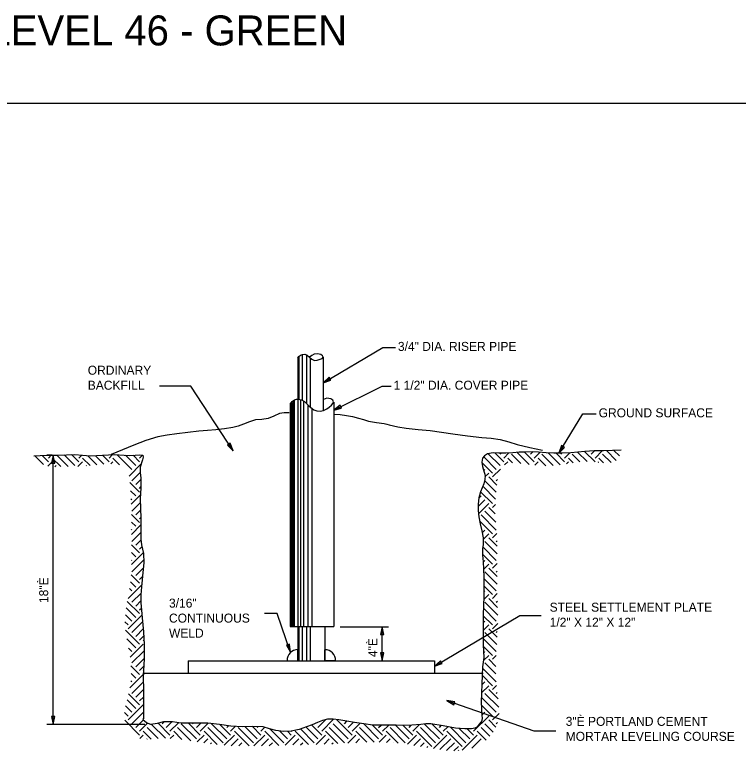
# Model space of a CAD drawing. Extents: x -439.1 to -407.9, y -458.1 to -436.2.
# Drawn here: x -426.04 to -413.98, y -448.69 to -436.2 of the extents above; entities that cross this region are included whole.
import ezdxf

# ---------------------------------------------------------------- set-up
doc = ezdxf.new("R2010")
doc.units = 0
for name, color, linetype in [('Bridge-Named Boundary', 7, 'Continuous'), ('Default', 7, 'Continuous'), ('Level 4', 7, 'Continuous'), ('Level 46', 7, 'Continuous')]:
    doc.layers.add(name, color=color, linetype=linetype)

msp = doc.modelspace()

# ---------------------------------------------------------------- linework, layer by layer
at = {"layer": 'Bridge-Named Boundary'}
msp.add_lwpolyline([(-439.109, -458.051), (-407.859, -458.051), (-407.859, -437.676), (-439.109, -437.676)], close=True, dxfattribs=at)
at = {"layer": 'Default'}
for p, q in [((-420.903, -442.33), (-419.904, -441.741)), ((-419.904, -441.741), (-419.695, -441.741)), ((-421.306, -441.894), (-421.306, -442.605)), ((-421.254, -441.859), (-421.254, -442.619)), ((-421.18, -441.866), (-421.18, -442.673)), ((-421.116, -441.915), (-421.116, -442.739)), ((-420.903, -442.33), (-420.79, -442.263)), ((-420.79, -442.263), (-420.903, -442.33)), ((-423.108, -442.387), (-423.634, -442.387)), ((-422.404, -443.465), (-423.108, -442.387)), ((-420.725, -442.79), (-419.918, -442.387)), ((-419.918, -442.387), (-419.767, -442.387)), ((-421.324, -442.604), (-421.324, -446.398)), ((-421.429, -442.664), (-421.429, -446.398)), ((-421.408, -442.642), (-421.408, -446.398)), ((-421.387, -442.623), (-421.387, -446.398)), ((-421.282, -442.61), (-421.282, -446.398)), ((-421.23, -442.632), (-421.23, -446.398)), ((-421.156, -442.698), (-421.156, -446.398)), ((-421.092, -442.76), (-421.092, -446.398)), ((-420.725, -442.79), (-420.607, -442.731)), ((-420.607, -442.731), (-420.725, -442.79)), ((-416.971, -443.507), (-416.57, -442.847)), ((-416.57, -442.847), (-416.347, -442.847)), ((-422.404, -443.465), (-422.476, -443.355)), ((-422.476, -443.355), (-422.404, -443.465)), ((-416.902, -443.394), (-416.971, -443.507)), ((-416.971, -443.507), (-416.902, -443.394)), ((-416.368, -443.649), (-416.542, -443.476)), ((-416.432, -443.523), (-416.38, -443.47)), ((-416.368, -443.586), (-416.249, -443.466)), ((-416.013, -443.625), (-416.174, -443.463)), ((-415.959, -443.552), (-416.052, -443.459)), ((-415.989, -443.459), (-415.986, -443.457)), ((-425.565, -443.695), (-425.711, -443.549)), ((-425.484, -443.649), (-425.59, -443.543)), ((-425.424, -443.539), (-425.511, -443.539)), ((-425.484, -443.586), (-425.437, -443.539)), ((-425.277, -443.729), (-425.421, -443.586)), ((-425.403, -448.028), (-425.403, -443.539)), ((-425.153, -443.727), (-425.341, -443.539)), ((-425.041, -443.712), (-425.22, -443.534)), ((-424.978, -443.649), (-425.099, -443.528)), ((-424.978, -443.586), (-424.929, -443.538)), ((-424.788, -443.712), (-424.914, -443.586)), ((-424.674, -443.7), (-424.826, -443.547)), ((-424.559, -443.688), (-424.699, -443.548)), ((-424.471, -443.649), (-424.581, -443.54)), ((-424.471, -443.586), (-424.414, -443.528)), ((-424.296, -443.698), (-424.408, -443.586)), ((-424.091, -443.776), (-424.337, -443.531)), ((-424.028, -443.712), (-424.199, -443.541)), ((-423.965, -443.649), (-424.073, -443.541)), ((-423.965, -443.586), (-423.917, -443.538)), ((-418.014, -443.776), (-418.223, -443.567)), ((-417.951, -443.712), (-418.148, -443.515)), ((-417.888, -443.649), (-418.034, -443.503)), ((-417.951, -443.523), (-417.935, -443.507)), ((-417.888, -443.586), (-417.804, -443.502)), ((-417.742, -443.668), (-417.824, -443.586)), ((-417.607, -443.677), (-417.761, -443.523)), ((-417.464, -443.693), (-417.664, -443.493)), ((-417.381, -443.649), (-417.543, -443.487)), ((-417.445, -443.523), (-417.408, -443.486)), ((-417.381, -443.586), (-417.284, -443.488)), ((-417.189, -443.714), (-417.318, -443.586)), ((-417.066, -443.711), (-417.255, -443.523)), ((-416.95, -443.7), (-417.15, -443.5)), ((-416.875, -443.649), (-417.017, -443.507)), ((-416.938, -443.523), (-416.923, -443.507)), ((-416.875, -443.586), (-416.787, -443.498)), ((-416.732, -443.665), (-416.812, -443.586)), ((-416.622, -443.649), (-416.748, -443.523)), ((-416.499, -443.646), (-416.658, -443.486)), ((-416.224, -443.667), (-416.305, -443.586)), ((-416.101, -443.663), (-416.242, -443.523)), ((-425.494, -443.722), (-425.421, -443.649)), ((-425.378, -443.733), (-425.357, -443.712)), ((-424.991, -443.726), (-424.914, -443.649)), ((-424.857, -443.718), (-424.851, -443.712)), ((-424.443, -443.684), (-424.408, -443.649)), ((-424.139, -443.887), (-423.936, -443.683)), ((-418.078, -443.839), (-418.254, -443.663)), ((-417.878, -443.702), (-417.824, -443.649)), ((-417.372, -443.703), (-417.318, -443.649)), ((-416.846, -443.683), (-416.812, -443.649)), ((-416.313, -443.657), (-416.305, -443.649)), ((-424.091, -443.966), (-423.955, -443.83)), ((-418.221, -443.793), (-418.204, -443.776)), ((-418.204, -443.902), (-418.141, -443.839)), ((-418.078, -443.902), (-417.945, -443.77)), ((-424.028, -444.029), (-423.942, -443.942)), ((-418.015, -444.154), (-418.204, -443.966)), ((-418.003, -444.04), (-418.141, -443.902)), ((-418.014, -443.966), (-417.992, -443.943)), ((-423.965, -444.156), (-424.127, -443.993)), ((-423.965, -444.092), (-423.94, -444.068)), ((-418.026, -444.271), (-418.239, -444.057)), ((-424.028, -444.219), (-424.116, -444.131)), ((-424.103, -444.357), (-423.948, -444.202)), ((-418.301, -444.252), (-418.268, -444.219)), ((-418.078, -444.345), (-418.275, -444.148)), ((-424.091, -444.282), (-424.107, -444.267)), ((-424.091, -444.472), (-423.953, -444.334)), ((-418.317, -444.395), (-418.204, -444.282)), ((-418.311, -444.516), (-418.141, -444.345)), ((-424.028, -444.535), (-423.948, -444.456)), ((-418.022, -444.654), (-418.204, -444.472)), ((-418.031, -444.519), (-418.141, -444.409)), ((-418.078, -444.409), (-418.03, -444.361)), ((-423.965, -444.662), (-424.099, -444.528)), ((-423.965, -444.599), (-423.942, -444.576)), ((-418.014, -444.789), (-418.268, -444.535)), ((-424.1, -444.86), (-423.942, -444.702)), ((-424.028, -444.725), (-424.098, -444.655)), ((-418.078, -444.852), (-418.291, -444.639)), ((-418.27, -444.728), (-418.268, -444.725)), ((-424.091, -444.789), (-424.099, -444.781)), ((-424.091, -444.978), (-423.942, -444.829)), ((-418.248, -444.833), (-418.204, -444.789)), ((-418.233, -444.944), (-418.141, -444.852)), ((-418.078, -444.915), (-418.006, -444.844)), ((-424.028, -445.042), (-423.939, -444.953)), ((-417.998, -445.185), (-418.204, -444.978)), ((-418, -445.057), (-418.141, -444.915)), ((-418.014, -444.978), (-418.001, -444.965)), ((-423.965, -445.168), (-424.099, -445.034)), ((-423.965, -445.105), (-423.925, -445.065)), ((-418.014, -445.295), (-418.239, -445.07)), ((-424.028, -445.232), (-424.098, -445.162)), ((-424.097, -445.364), (-423.902, -445.169)), ((-418.078, -445.358), (-418.245, -445.191)), ((-424.091, -445.295), (-424.096, -445.29)), ((-424.091, -445.485), (-423.896, -445.29)), ((-418.233, -445.323), (-418.204, -445.295)), ((-418.078, -445.422), (-417.999, -445.343)), ((-424.028, -445.548), (-423.903, -445.423)), ((-418.228, -445.445), (-418.141, -445.358)), ((-418.002, -445.561), (-418.141, -445.422)), ((-418.014, -445.485), (-418.001, -445.471)), ((-423.965, -445.675), (-424.105, -445.534)), ((-423.965, -445.612), (-423.916, -445.563)), ((-418.014, -445.801), (-418.222, -445.593)), ((-418.001, -445.688), (-418.204, -445.485)), ((-424.155, -445.928), (-423.928, -445.702)), ((-424.028, -445.738), (-424.113, -445.653)), ((-418.078, -445.865), (-418.222, -445.72)), ((-424.091, -445.801), (-424.129, -445.764)), ((-424.091, -445.991), (-423.938, -445.838)), ((-418.222, -445.82), (-418.204, -445.801)), ((-418.078, -445.928), (-417.998, -445.848)), ((-424.028, -446.055), (-423.941, -445.968)), ((-418.224, -445.948), (-418.141, -445.865)), ((-417.992, -446.077), (-418.141, -445.928)), ((-418.014, -445.991), (-417.995, -445.972)), ((-424.028, -446.245), (-424.186, -446.087)), ((-423.965, -446.181), (-424.168, -445.978)), ((-423.965, -446.118), (-423.934, -446.088)), ((-418.014, -446.308), (-418.23, -446.092)), ((-417.991, -446.205), (-418.204, -445.991)), ((-424.091, -446.308), (-424.2, -446.2)), ((-424.155, -446.434), (-423.925, -446.205)), ((-421.671, -446.181), (-421.88, -446.181)), ((-421.446, -446.827), (-421.671, -446.181)), ((-419.043, -447.058), (-417.619, -446.21)), ((-418.078, -446.371), (-418.233, -446.216)), ((-417.619, -446.21), (-417.267, -446.21)), ((-424.155, -446.371), (-424.207, -446.319)), ((-424.091, -446.498), (-423.915, -446.321)), ((-418.233, -446.337), (-418.204, -446.308)), ((-418.078, -446.434), (-417.991, -446.348)), ((-423.965, -446.688), (-424.197, -446.455)), ((-424.028, -446.561), (-423.904, -446.437)), ((-421.306, -446.398), (-421.306, -446.967)), ((-421.254, -446.398), (-421.254, -446.967)), ((-421.18, -446.398), (-421.18, -446.967)), ((-421.116, -446.398), (-421.116, -446.967)), ((-420.62, -446.399), (-419.811, -446.399)), ((-419.915, -446.966), (-419.915, -446.399)), ((-418.234, -446.464), (-418.141, -446.371)), ((-418.001, -446.574), (-418.141, -446.434)), ((-423.965, -446.624), (-423.896, -446.556)), ((-418.014, -446.814), (-418.235, -446.594)), ((-418.006, -446.696), (-418.204, -446.498)), ((-418.014, -446.498), (-417.997, -446.48)), ((-424.028, -446.751), (-424.175, -446.604)), ((-424.122, -446.908), (-423.901, -446.688)), ((-423.892, -446.634), (-423.901, -446.624)), ((-421.49, -446.7), (-421.447, -446.825)), ((-421.447, -446.825), (-421.49, -446.7)), ((-418.078, -446.878), (-418.231, -446.724)), ((-424.091, -446.814), (-424.146, -446.759)), ((-424.091, -447.004), (-423.889, -446.802)), ((-421.324, -446.967), (-421.324, -446.781)), ((-420.873, -446.967), (-420.873, -446.784)), ((-418.224, -446.834), (-418.204, -446.814)), ((-424.028, -447.067), (-423.889, -446.929)), ((-421.505, -446.967), (-421.324, -446.967)), ((-420.694, -446.967), (-420.873, -446.967)), ((-418.228, -446.964), (-418.141, -446.878)), ((-418.021, -447.061), (-418.141, -446.941)), ((-418.078, -446.941), (-418.014, -446.877)), ((-423.965, -447.194), (-424.109, -447.05)), ((-423.965, -447.131), (-423.896, -447.062)), ((-418.015, -447.32), (-418.245, -447.09)), ((-418.02, -447.188), (-418.204, -447.004)), ((-424.125, -447.418), (-423.901, -447.194)), ((-424.028, -447.257), (-424.105, -447.18)), ((-423.9, -447.133), (-423.901, -447.131)), ((-418.078, -447.384), (-418.252, -447.209)), ((-424.091, -447.321), (-424.109, -447.303)), ((-424.091, -447.511), (-423.9, -447.319)), ((-418.254, -447.371), (-418.204, -447.321)), ((-424.028, -447.574), (-423.9, -447.446)), ((-418.26, -447.503), (-418.141, -447.384)), ((-417.985, -447.603), (-418.141, -447.447)), ((-418.078, -447.447), (-418.012, -447.382)), ((-423.965, -447.701), (-424.146, -447.519)), ((-423.965, -447.637), (-423.9, -447.572)), ((-418.014, -447.827), (-418.263, -447.579)), ((-417.971, -447.744), (-418.204, -447.511)), ((-418.014, -447.511), (-417.998, -447.495)), ((-424.091, -447.827), (-424.198, -447.721)), ((-424.028, -447.764), (-424.172, -447.619)), ((-424.155, -447.954), (-423.901, -447.701)), ((-423.9, -447.639), (-423.901, -447.637)), ((-418.84, -447.632), (-417.389, -448.135)), ((-418.84, -447.632), (-418.716, -447.676)), ((-418.716, -447.676), (-418.84, -447.632)), ((-418.078, -447.89), (-418.262, -447.706)), ((-424.155, -447.89), (-424.216, -447.829)), ((-424.091, -448.017), (-423.9, -447.826)), ((-418.254, -447.877), (-418.204, -447.827)), ((-418.078, -447.954), (-417.969, -447.846)), ((-423.965, -448.207), (-424.212, -447.96)), ((-424.028, -448.08), (-423.906, -447.958)), ((-420.99, -448.08), (-420.861, -447.952)), ((-420.926, -448.144), (-420.727, -447.944)), ((-420.42, -448.207), (-420.673, -447.954)), ((-420.546, -448.017), (-420.506, -447.976)), ((-418.394, -448.144), (-418.141, -447.89)), ((-418.02, -448.075), (-418.141, -447.954)), ((-423.878, -448.028), (-425.511, -448.028)), ((-423.965, -448.144), (-423.829, -448.008)), ((-423.653, -448.266), (-423.838, -448.08)), ((-423.532, -448.26), (-423.764, -448.028)), ((-423.458, -448.207), (-423.655, -448.011)), ((-423.585, -448.017), (-423.554, -447.986)), ((-423.522, -448.08), (-423.427, -447.986)), ((-423.458, -448.144), (-423.315, -448.001)), ((-423.111, -448.301), (-423.332, -448.08)), ((-423.015, -448.27), (-423.268, -448.017)), ((-422.952, -448.207), (-423.148, -448.011)), ((-423.079, -448.017), (-423.07, -448.008)), ((-423.015, -448.08), (-422.943, -448.008)), ((-422.952, -448.144), (-422.819, -448.011)), ((-422.572, -448.334), (-422.825, -448.08)), ((-422.509, -448.27), (-422.762, -448.017)), ((-422.446, -448.207), (-422.624, -448.029)), ((-422.509, -448.08), (-422.478, -448.05)), ((-422.446, -448.144), (-422.363, -448.061)), ((-422.066, -448.334), (-422.319, -448.08)), ((-422.002, -448.27), (-422.204, -448.068)), ((-421.939, -448.207), (-422.083, -448.063)), ((-422.002, -448.08), (-421.985, -448.063)), ((-421.939, -448.144), (-421.873, -448.077)), ((-420.99, -448.27), (-421.186, -448.073)), ((-420.926, -448.207), (-421.096, -448.037)), ((-420.546, -448.334), (-420.8, -448.08)), ((-420.483, -448.27), (-420.736, -448.017)), ((-420.483, -448.08), (-420.396, -447.994)), ((-420.42, -448.144), (-420.288, -448.012)), ((-420.049, -448.324), (-420.293, -448.08)), ((-419.977, -448.27), (-420.224, -448.022)), ((-419.913, -448.207), (-420.083, -448.038)), ((-419.977, -448.08), (-419.936, -448.04)), ((-419.913, -448.144), (-419.808, -448.039)), ((-419.534, -448.334), (-419.787, -448.08)), ((-419.47, -448.27), (-419.697, -448.044)), ((-419.407, -448.207), (-419.565, -448.049)), ((-419.47, -448.08), (-419.434, -448.044)), ((-419.407, -448.144), (-419.294, -448.03)), ((-419.027, -448.334), (-419.28, -448.08)), ((-418.964, -448.27), (-419.21, -448.024)), ((-418.901, -448.207), (-419.088, -448.019)), ((-418.964, -448.08), (-418.927, -448.044)), ((-418.901, -448.144), (-418.824, -448.067)), ((-418.521, -448.334), (-418.774, -448.08)), ((-418.457, -448.27), (-418.632, -448.095)), ((-418.121, -448.227), (-418.268, -448.08)), ((-418.064, -448.157), (-418.204, -448.017)), ((-418.014, -448.017), (-417.993, -447.995)), ((-423.958, -448.263), (-423.901, -448.207)), ((-423.771, -448.274), (-423.901, -448.144)), ((-423.451, -448.263), (-423.395, -448.207)), ((-423.26, -448.279), (-423.395, -448.144)), ((-423.001, -448.32), (-422.889, -448.207)), ((-422.667, -448.365), (-422.889, -448.144)), ((-422.551, -448.375), (-422.382, -448.207)), ((-422.137, -448.389), (-422.382, -448.144)), ((-422.058, -448.389), (-421.876, -448.207)), ((-421.64, -448.379), (-421.876, -448.144)), ((-421.559, -448.334), (-421.79, -448.103)), ((-421.496, -448.27), (-421.625, -448.142)), ((-421.538, -448.376), (-421.369, -448.207)), ((-421.433, -448.207), (-421.495, -448.144)), ((-421.433, -448.144), (-421.428, -448.139)), ((-421.148, -448.365), (-421.369, -448.144)), ((-421.053, -448.334), (-421.282, -448.105)), ((-421.018, -448.362), (-420.863, -448.207)), ((-420.657, -448.35), (-420.863, -448.144)), ((-420.491, -448.342), (-420.357, -448.207)), ((-420.173, -448.327), (-420.357, -448.144)), ((-419.966, -448.323), (-419.85, -448.207)), ((-419.65, -448.343), (-419.85, -448.144)), ((-419.498, -448.361), (-419.344, -448.207)), ((-419.09, -448.397), (-419.344, -448.144)), ((-419.063, -448.433), (-418.837, -448.207)), ((-418.584, -448.397), (-418.837, -448.144)), ((-418.584, -448.46), (-418.331, -448.207)), ((-418.394, -448.207), (-418.498, -448.103)), ((-418.185, -448.29), (-418.331, -448.144)), ((-417.389, -448.135), (-417.023, -448.135)), ((-423.843, -448.275), (-423.838, -448.27)), ((-422.891, -448.336), (-422.825, -448.27)), ((-422.78, -448.352), (-422.762, -448.334)), ((-422.434, -448.385), (-422.319, -448.27)), ((-422.309, -448.387), (-422.256, -448.334)), ((-421.931, -448.389), (-421.812, -448.27)), ((-421.8, -448.385), (-421.749, -448.334)), ((-421.408, -448.372), (-421.306, -448.27)), ((-421.277, -448.368), (-421.243, -448.334)), ((-420.887, -448.358), (-420.8, -448.27)), ((-420.756, -448.354), (-420.736, -448.334)), ((-420.358, -448.335), (-420.293, -448.27)), ((-419.846, -448.329), (-419.787, -448.27)), ((-419.725, -448.335), (-419.724, -448.334)), ((-419.388, -448.378), (-419.28, -448.27)), ((-419.279, -448.396), (-419.217, -448.334)), ((-418.954, -448.45), (-418.774, -448.27)), ((-418.842, -448.464), (-418.711, -448.334)), ((-418.425, -448.427), (-418.268, -448.27)), ((-419.171, -448.414), (-419.154, -448.397)), ((-418.722, -448.471), (-418.647, -448.397)), ((-418.639, -448.468), (-418.647, -448.46))]:
    msp.add_line(p, q, dxfattribs=at)
for points in [[(-420.804, -442.239), (-420.904, -442.33), (-420.776, -442.287)], [(-420.619, -442.706), (-420.725, -442.79), (-420.594, -442.755)], [(-422.499, -443.37), (-422.404, -443.465), (-422.453, -443.34)], [(-416.926, -443.38), (-416.971, -443.507), (-416.879, -443.409)], [(-425.376, -443.671), (-425.403, -443.539), (-425.431, -443.671)], [(-419.888, -446.531), (-419.915, -446.399), (-419.943, -446.531)], [(-421.516, -446.709), (-421.447, -446.825), (-421.464, -446.691)], [(-419.943, -446.835), (-419.915, -446.967), (-419.888, -446.835)], [(-418.944, -446.967), (-419.043, -447.058), (-418.915, -447.014)], [(-418.944, -446.967), (-419.043, -447.058), (-418.915, -447.014)], [(-418.707, -447.65), (-418.84, -447.632), (-418.724, -447.702)], [(-425.431, -447.896), (-425.403, -448.028), (-425.376, -447.896)], [(-418.328, -448.07), (-418.262, -447.984)]]:
    msp.add_lwpolyline(points, close=True, dxfattribs=at)
for points in [[(-420.79, -442.263), (-420.804, -442.239), (-420.904, -442.33), (-420.903, -442.33)], [(-420.903, -442.33), (-420.776, -442.287)], [(-420.776, -442.287), (-420.79, -442.263)], [(-420.607, -442.731), (-420.619, -442.706), (-420.725, -442.79)], [(-420.725, -442.79), (-420.594, -442.755)], [(-420.594, -442.755), (-420.607, -442.731)], [(-422.476, -443.355), (-422.499, -443.37), (-422.404, -443.465)], [(-422.404, -443.465), (-422.453, -443.34), (-422.476, -443.355)], [(-416.902, -443.394), (-416.926, -443.38), (-416.971, -443.507)], [(-416.971, -443.507), (-416.879, -443.409), (-416.902, -443.394)], [(-421.49, -446.7), (-421.516, -446.709), (-421.447, -446.825)], [(-421.447, -446.825), (-421.464, -446.691), (-421.49, -446.7)], [(-418.716, -447.676), (-418.707, -447.65), (-418.84, -447.632)], [(-418.84, -447.632), (-418.724, -447.702)], [(-418.724, -447.702), (-418.716, -447.676)], [(-423.902, -447.927), (-423.906, -447.941), (-423.91, -447.955)], [(-418.328, -448.07), (-418.295, -448.027), (-418.262, -447.984)]]:
    msp.add_lwpolyline(points, dxfattribs=at)
for centre, start, end in [((-421.326, -446.96), 89.4157, 181.9788), ((-421.326, -446.96), 89.4306, 182.0652), ((-420.873, -446.963), 358.8255, 90), ((-420.873, -446.963), 358.7391, 90.1704)]:
    msp.add_arc(centre, 0.179, start, end, dxfattribs=at)
at = {"layer": 'Level 4'}
for p, q in [((-421.324, -441.922), (-421.324, -442.604)), ((-420.904, -441.906), (-420.904, -442.794)), ((-421.451, -442.686), (-421.451, -446.398)), ((-420.725, -442.654), (-420.725, -446.398)), ((-421.451, -446.398), (-420.725, -446.398)), ((-421.324, -446.398), (-421.324, -446.967)), ((-420.874, -446.398), (-420.874, -446.967)), ((-423.154, -446.967), (-423.154, -447.177)), ((-423.154, -446.967), (-419.043, -446.967)), ((-419.043, -446.967), (-419.043, -447.177)), ((-423.911, -447.177), (-418.232, -447.177))]:
    msp.add_line(p, q, dxfattribs=at)
for points in [[(-421.324, -441.922), (-421.306, -441.894), (-421.281, -441.871), (-421.246, -441.857), (-421.209, -441.856), (-421.167, -441.873), (-421.13, -441.903), (-421.088, -441.938), (-421.044, -441.96), (-421, -441.956), (-420.95, -441.938), (-420.92, -441.924), (-420.903, -441.906), (-420.914, -441.883), (-420.94, -441.862), (-420.996, -441.846), (-421.051, -441.856), (-421.093, -441.875), (-421.13, -441.903)], [(-421.45, -442.686), (-421.42, -442.646), (-421.379, -442.617), (-421.348, -442.606), (-421.316, -442.604), (-421.261, -442.616), (-421.212, -442.645), (-421.136, -442.719), (-421.057, -442.784), (-421.007, -442.8), (-420.953, -442.803), (-420.895, -442.792), (-420.842, -442.768), (-420.802, -442.74), (-420.763, -442.705), (-420.74, -442.679), (-420.729, -442.651), (-420.743, -442.621), (-420.776, -442.598), (-420.838, -442.59), (-420.896, -442.61)], [(-421.471, -442.834), (-421.551, -442.833), (-421.629, -442.845), (-421.724, -442.888), (-421.818, -442.929), (-421.922, -442.942), (-422.028, -442.95), (-422.129, -442.982), (-422.228, -443.024), (-422.317, -443.054), (-422.407, -443.076), (-422.548, -443.102), (-422.691, -443.118), (-422.833, -443.129), (-422.975, -443.139), (-423.159, -443.158), (-423.343, -443.181), (-423.501, -443.204), (-423.658, -443.234), (-423.86, -443.295), (-424.058, -443.371), (-424.248, -443.447), (-424.436, -443.528)], [(-420.725, -442.856), (-420.619, -442.863), (-420.514, -442.877), (-420.414, -442.894), (-420.315, -442.919), (-420.231, -442.946), (-420.146, -442.971), (-420.015, -442.993), (-419.884, -443.013), (-419.841, -443.023), (-419.8, -443.034), (-419.658, -443.065), (-419.516, -443.087), (-419.316, -443.109), (-419.116, -443.129), (-418.927, -443.153), (-418.738, -443.181), (-418.497, -443.217), (-418.254, -443.245), (-418.101, -443.256), (-417.949, -443.276), (-417.807, -443.315), (-417.665, -443.36), (-417.456, -443.413), (-417.245, -443.455)], [(-415.931, -443.455), (-416.078, -443.46), (-416.225, -443.465), (-416.383, -443.469), (-416.54, -443.476), (-416.656, -443.486), (-416.772, -443.497), (-416.914, -443.507), (-417.055, -443.507), (-417.182, -443.497), (-417.308, -443.486), (-417.418, -443.484), (-417.529, -443.486), (-417.634, -443.49), (-417.739, -443.497), (-417.854, -443.506), (-417.97, -443.507), (-418.066, -443.502), (-418.159, -443.518), (-418.209, -443.548), (-418.244, -443.591), (-418.256, -443.656), (-418.242, -443.727), (-418.201, -443.875), (-418.204, -443.946), (-418.222, -444.014), (-418.275, -444.149), (-418.303, -444.252), (-418.317, -444.358), (-418.318, -444.464), (-418.307, -444.569), (-418.282, -444.685), (-418.254, -444.801), (-418.233, -444.916), (-418.233, -445.032), (-418.238, -445.063), (-418.244, -445.095), (-418.245, -445.205), (-418.233, -445.316), (-418.225, -445.442), (-418.222, -445.568), (-418.221, -445.731), (-418.222, -445.894), (-418.228, -446.046), (-418.233, -446.199), (-418.233, -446.299), (-418.233, -446.399), (-418.236, -446.551), (-418.233, -446.703), (-418.225, -446.809), (-418.222, -446.914), (-418.232, -446.993), (-418.244, -447.071), (-418.252, -447.213), (-418.254, -447.355), (-418.26, -447.508), (-418.265, -447.66), (-418.262, -447.77), (-418.254, -447.881), (-418.251, -447.923), (-418.254, -447.965), (-418.281, -448.025), (-418.328, -448.07), (-418.375, -448.092), (-418.428, -448.102), (-418.538, -448.102), (-418.618, -448.098), (-418.696, -448.091), (-418.9, -448.05), (-419.106, -448.018), (-419.19, -448.02), (-419.274, -448.028), (-419.421, -448.043), (-419.568, -448.049), (-419.684, -448.044), (-419.8, -448.039), (-419.936, -448.04), (-420.073, -448.039), (-420.226, -448.022), (-420.378, -447.997), (-420.509, -447.975), (-420.641, -447.955), (-420.736, -447.943), (-420.83, -447.944), (-420.915, -447.965), (-420.998, -447.997), (-421.087, -448.034), (-421.177, -448.07), (-421.303, -448.112), (-421.433, -448.14), (-421.564, -448.149), (-421.692, -448.133), (-421.797, -448.101), (-421.902, -448.07), (-422.074, -448.062), (-422.249, -448.07), (-422.439, -448.056), (-422.628, -448.028), (-422.827, -448.01), (-423.027, -448.007), (-423.148, -448.011)], [(-425.729, -443.549), (-425.619, -443.542), (-425.508, -443.539), (-425.414, -443.539), (-425.319, -443.539), (-425.182, -443.532), (-425.046, -443.528), (-424.915, -443.539), (-424.783, -443.549), (-424.58, -443.539), (-424.383, -443.528), (-424.221, -443.54), (-424.134, -443.544), (-424.036, -443.539), (-423.962, -443.531), (-423.91, -443.539), (-423.901, -443.57), (-423.913, -443.619), (-423.952, -443.739), (-423.956, -443.832), (-423.942, -443.917), (-423.94, -444.088), (-423.952, -444.264), (-423.95, -444.428), (-423.942, -444.59), (-423.941, -444.716), (-423.942, -444.843), (-423.941, -444.938), (-423.931, -445.032), (-423.915, -445.105), (-423.9, -445.179), (-423.895, -445.336), (-423.91, -445.494), (-423.922, -445.615), (-423.931, -445.736), (-423.94, -445.868), (-423.942, -445.999), (-423.934, -446.125), (-423.921, -446.251), (-423.909, -446.367), (-423.9, -446.483), (-423.893, -446.588), (-423.889, -446.693), (-423.887, -446.814), (-423.889, -446.935), (-423.895, -447.035), (-423.9, -447.135), (-423.901, -447.276), (-423.9, -447.418), (-423.9, -447.503), (-423.9, -447.587), (-423.9, -447.681), (-423.9, -447.776), (-423.9, -447.855), (-423.9, -447.934)], [(-423.148, -448.011), (-423.269, -448.007), (-423.416, -447.986), (-423.563, -447.986), (-423.669, -448.016), (-423.774, -448.028), (-423.846, -448.002), (-423.91, -447.955)]]:
    msp.add_lwpolyline(points, dxfattribs=at)

# ---------------------------------------------------------------- texts
at = {"layer": 'Default'}
for s, p in [('3/4" DIA. RISER PIPE', (-419.655, -441.8)), ('ORDINARY ', (-424.828, -442.197)), ('BACKFILL', (-424.828, -442.447)), ('1 1/2" DIA. COVER PIPE ', (-419.727, -442.447)), ('GROUND SURFACE', (-416.307, -442.907)), ('3/16" ', (-423.473, -446.081)), ('STEEL SETTLEMENT PLATE ', (-417.124, -446.149)), ('CONTINUOUS ', (-423.473, -446.331)), ('1/2" X 12" X 12"', (-417.124, -446.399)), ('WELD', (-423.473, -446.581)), ('3"È PORTLAND CEMENT ', (-416.857, -448.053)), ('MORTAR LEVELING COURSE', (-416.857, -448.303))]:
    msp.add_text(s, height=0.15, dxfattribs=at).set_placement(p)
for s, p in [('18"È', (-425.488, -446.005)), ('4"È', (-420, -446.906))]:
    msp.add_text(s, height=0.15, rotation=90, dxfattribs=at).set_placement(p)
at = {"layer": 'Level 46'}
msp.add_text('METRIC - LEVEL 46 - GREEN', height=0.5, dxfattribs=at).set_placement((-429.642, -436.705))

doc.saveas('drawing.dxf')
